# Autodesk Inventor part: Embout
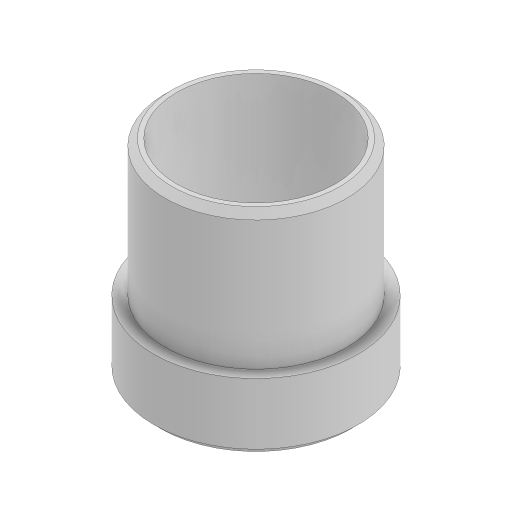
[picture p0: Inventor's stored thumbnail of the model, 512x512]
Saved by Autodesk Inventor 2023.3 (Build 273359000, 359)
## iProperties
Created: 2024-11
Part Number: Embout
Material: Générique
Description: STEP AP203
Document SubType Name: Modeling
Designer: Thier
Density: 1 g/cm^3
Appearance: Par défaut
Title: Embout.STEP
Revision Number: ANY
Sending System: SolidWorks 2017
Preprocessor: SwSTEP 2.0
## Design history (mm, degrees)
feature "Chanfrein2"
node "Solide1"
